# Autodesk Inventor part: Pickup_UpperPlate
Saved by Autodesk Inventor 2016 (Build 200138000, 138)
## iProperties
Created: 2016-01
Part Number: Pickup_UpperPlate
Material: Generic
Document SubType Name: Modeling
Designer: Juha-Pekka
Density: 1 g/cm^3
Appearance: Default
Author: Juha-Pekka
Revision Number: ANY
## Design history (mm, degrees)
fillet "Fillet1"
body "Solid1"
